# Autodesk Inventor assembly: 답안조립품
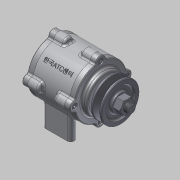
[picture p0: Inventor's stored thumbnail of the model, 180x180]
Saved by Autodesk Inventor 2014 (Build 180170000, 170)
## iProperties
Created: 2015-03
Part Number: 답안조립품
Document SubType Name: Assembly
Designer: MYHOME
Author: MYHOME
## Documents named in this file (11)
- C:\Documents and Settings\MYHOME\바탕 화면\450306V1024\답안조립품.iam
- C:\Documents and Settings\MYHOME\바탕 화면\450306V1024\본체.ipt
- C:\Documents and Settings\MYHOME\바탕 화면\450306V1024\커버.ipt
- C:\Documents and Settings\MYHOME\바탕 화면\450306V1024\커버2.ipt
- C:\Documents and Settings\MYHOME\바탕 화면\450306V1024\M 4 x 12.ipt
- C:\Documents and Settings\MYHOME\바탕 화면\450306V1024\오일실.ipt
- C:\Documents and Settings\MYHOME\바탕 화면\450306V1024\축.ipt
- C:\Documents and Settings\MYHOME\바탕 화면\450306V1024\키(4 x 4 x 12).ipt
- C:\Documents and Settings\MYHOME\바탕 화면\450306V1024\베어링 6204.ipt
- C:\Documents and Settings\MYHOME\바탕 화면\450306V1024\V벨트풀리.ipt
- C:\Documents and Settings\MYHOME\바탕 화면\450306V1024\너트 M12x1.25.ipt
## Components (14 placed, 6 different names)
1. KS B 2804 D D - 20 32 8:1
2. KS B 1311 (I) 4 x 4 x 12:1
3. KS B 2023 6204 - 20 x 47 x 14:1 — 각도:3
4. KS B 2023 6204 - 20 x 47 x 14:2 — 각도:4
5. 그루브 풀리1:1
6. KS B 1012 클래스 1 일반 - 미터 M12x1.25:1 — 각도:2
7. KS B 1003 - 미터 M 4 x 12:1
8. KS B 1003 - 미터 M 4 x 12:3
9. KS B 1003 - 미터 M 4 x 12:4
10. KS B 1003 - 미터 M 4 x 12:5
11. KS B 1003 - 미터 M 4 x 12:2
12. KS B 1003 - 미터 M 4 x 12:6
13. KS B 1003 - 미터 M 4 x 12:7
14. KS B 1003 - 미터 M 4 x 12:8
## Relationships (3: Angle 3)
- 각도:2 [Angle]: KS B 1012 클래스 1 일반 - 미터 M12x1.25:1
- 각도:3 [Angle]: KS B 2023 6204 - 20 x 47 x 14:1
- 각도:4 [Angle]: KS B 2023 6204 - 20 x 47 x 14:2
